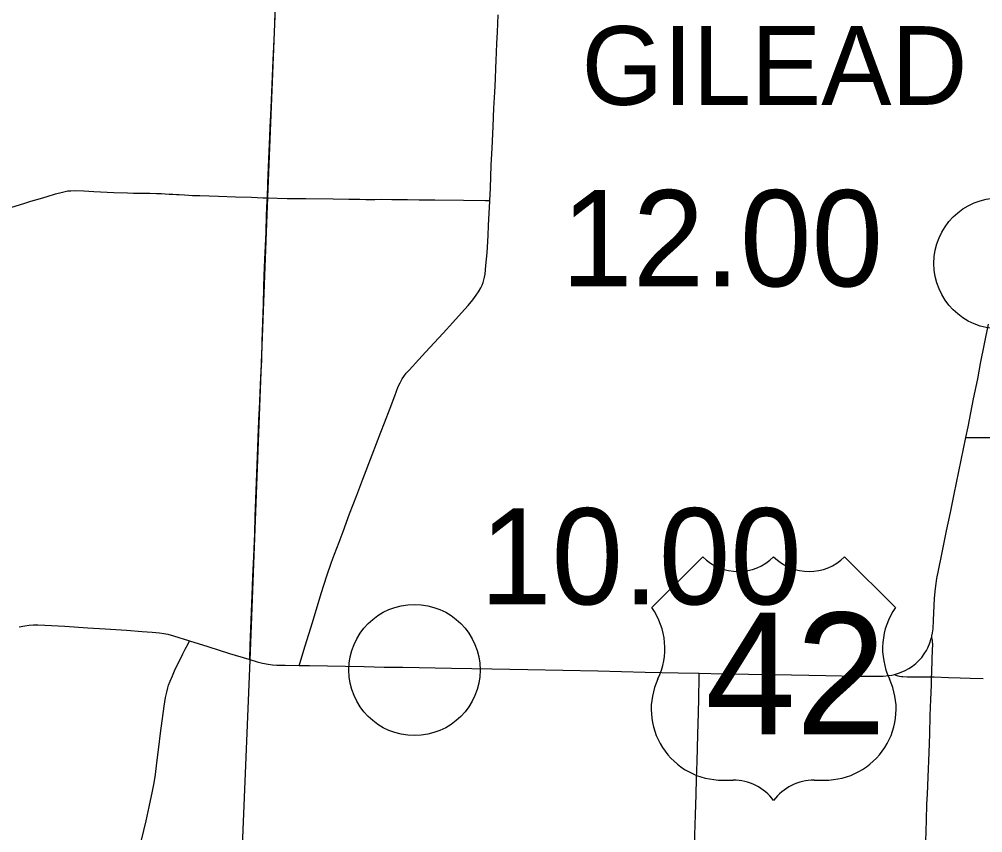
# Model space of a CAD drawing. Extents: x 1813937 to 1948437, y 826606 to 1022856.
# Drawn here: x 1864595 to 1875617, y 914870 to 924169 of the extents above; entities that cross this region are included whole.
import ezdxf

# ---------------------------------------------------------------- set-up
doc = ezdxf.new("R2010")
doc.units = 0
for name, color, linetype in [('Default', 7, 'Continuous'), ('GM_X_County_Road', 7, 'Continuous'), ('GM_X_Township', 7, 'Continuous'), ('GM_X_Township_Road', 7, 'Continuous'), ('GM_X_Township_Text', 7, 'Continuous'), ('GM_X_US_Route', 7, 'Continuous'), ('GM_X_US_Shield', 7, 'Continuous')]:
    doc.layers.add(name, color=color, linetype=linetype)

msp = doc.modelspace()

# ---------------------------------------------------------------- linework, layer by layer
at = {"layer": 'Default'}
for centre in [(1875809, 921379), (1869116, 916730)]:
    msp.add_circle(centre, 750, dxfattribs=at)
at = {"layer": 'GM_X_County_Road'}
for points in [[(1867433, 922128), (1867439, 922291), (1867450, 922570), (1867453, 922656), (1867457, 922749), (1867460, 922820), (1867466, 922939), (1867472, 923072), (1867480, 923243), (1867499, 923702), (1867513, 924013), (1867525, 924358), (1867534, 924555), (1867545, 924833), (1867550, 924964), (1867552, 925030), (1867558, 925194), (1867568, 925473), (1867576, 925670), (1867591, 926031), (1867595, 926158)], [(1867232, 916849), (1867232, 916867), (1867238, 917010), (1867259, 917584), (1867268, 917798), (1867277, 918027), (1867288, 918290), (1867294, 918486), (1867309, 918880), (1867321, 919175), (1867331, 919487), (1867340, 919670), (1867342, 919710), (1867350, 919897), (1867359, 920077), (1867368, 920274), (1867374, 920487), (1867381, 920701), (1867388, 920914), (1867393, 921111), (1867398, 921242), (1867406, 921422), (1867418, 921734), (1867425, 921931), (1867431, 922095), (1867433, 922128)], [(1875032, 916651), (1875034, 916687), (1875040, 916867), (1875045, 917030), (1875044, 917049), (1875041, 917073), (1875035, 917100), (1875033, 917111)], [(1874936, 914014), (1874938, 914048), (1874941, 914179), (1874951, 914424), (1874959, 914654), (1874965, 914769), (1874973, 915014), (1874979, 915195), (1874985, 915309), (1874992, 915506), (1875003, 915785), (1875010, 915998), (1875017, 916211), (1875023, 916392), (1875029, 916556), (1875032, 916651)]]:
    msp.add_lwpolyline(points, dxfattribs=at)
at = {"layer": 'GM_X_Township'}
msp.add_lwpolyline([(1862529, 931646), (1862452, 926319), (1863806, 926284), (1864501, 926257), (1864642, 926260), (1866861, 926186), (1867410, 926171), (1867588, 926156), (1867590, 926005), (1867433, 922134), (1867234, 916844), (1867123, 914163), (1866935, 910696)], dxfattribs=at)
at = {"layer": 'GM_X_Township_Road'}
for points in [[(1869978, 922096), (1869984, 922238), (1869995, 922500), (1870004, 922697), (1870015, 922942), (1870025, 923155), (1870036, 923336), (1870043, 923483), (1870047, 923614), (1870050, 923696), (1870059, 923893), (1870065, 924024), (1870072, 924220)], [(1864460, 922006), (1864648, 922065), (1864726, 922089), (1864836, 922121), (1864915, 922144), (1865009, 922172), (1865088, 922194), (1865120, 922201), (1865152, 922207), (1865185, 922209), (1865234, 922211), (1865332, 922208), (1865447, 922202), (1865677, 922189), (1865832, 922184), (1865903, 922183), (1865939, 922182), (1865982, 922181), (1866035, 922181), (1866088, 922180), (1866165, 922179), (1866223, 922176), (1866263, 922174), (1866309, 922171), (1866352, 922170), (1866392, 922168), (1866425, 922166), (1866485, 922162), (1866533, 922158), (1866578, 922155), (1866659, 922153), (1866873, 922148), (1867070, 922141), (1867250, 922134), (1867381, 922130), (1867433, 922128)], [(1867433, 922128), (1867660, 922122), (1867873, 922120), (1868185, 922118), (1868366, 922114), (1868490, 922112), (1868558, 922111), (1868661, 922111), (1868743, 922112), (1868858, 922110), (1869038, 922108), (1869170, 922107), (1869350, 922104), (1869678, 922101), (1869925, 922097), (1869978, 922096)], [(1867798, 916781), (1867805, 916804), (1867866, 917007), (1867948, 917274), (1868048, 917603), (1868114, 917806), (1868167, 917961), (1868200, 918054), (1868253, 918192), (1868299, 918314), (1868374, 918514), (1868457, 918729), (1868526, 918913), (1868631, 919189), (1868732, 919449), (1868774, 919556), (1868837, 919725), (1868890, 919863), (1868931, 919970), (1868951, 920014), (1868975, 920057), (1868993, 920084), (1869022, 920123), (1869055, 920159), (1869167, 920279), (1869244, 920364), (1869444, 920581), (1869554, 920703), (1869654, 920812), (1869730, 920898), (1869782, 920961), (1869822, 921014), (1869850, 921055), (1869874, 921098), (1869889, 921128), (1869902, 921159), (1869911, 921190), (1869919, 921223), (1869924, 921255), (1869934, 921353), (1869948, 921500), (1869952, 921566), (1869959, 921697), (1869964, 921812), (1869978, 922090), (1869978, 922096)], [(1875425, 919388), (1875471, 919389), (1875570, 919389), (1875750, 919387)], [(1865994, 914783), (1866045, 915007), (1866080, 915167), (1866119, 915343), (1866138, 915439), (1866153, 915536), (1866169, 915667), (1866191, 915846), (1866211, 916008), (1866254, 916317), (1866269, 916414), (1866282, 916478), (1866294, 916526), (1866304, 916557), (1866321, 916603), (1866347, 916663), (1866380, 916738), (1866423, 916826), (1866466, 916915), (1866494, 916969), (1866526, 917031), (1866542, 917064)], [(1872301, 914032), (1872302, 914059), (1872305, 914141), (1872314, 914436), (1872318, 914633), (1872324, 914846), (1872332, 915076), (1872339, 915305), (1872343, 915486), (1872349, 915683), (1872358, 915994), (1872364, 916240), (1872368, 916404), (1872373, 916650), (1872374, 916692)], [(1874606, 916678), (1874624, 916671), (1874645, 916663), (1874663, 916659), (1874686, 916655), (1874702, 916654), (1874752, 916652), (1874867, 916651), (1875032, 916651)], [(1875032, 916651), (1875063, 916651), (1875227, 916644), (1875358, 916640), (1875473, 916637), (1875621, 916634)]]:
    msp.add_lwpolyline(points, dxfattribs=at)
at = {"layer": 'GM_X_US_Route'}
for points in [[(1874996, 917002), (1875007, 917028), (1875028, 917091), (1875033, 917111), (1875036, 917122), (1875042, 917154), (1875048, 917202), (1875054, 917300), (1875065, 917546), (1875071, 917628), (1875079, 917694), (1875092, 917775), (1875141, 918016), (1875184, 918225), (1875204, 918321), (1875247, 918530), (1875291, 918739), (1875425, 919388), (1875450, 919510), (1875513, 919832), (1875559, 920057), (1875593, 920235), (1875682, 920685)], [(1864593, 917223), (1864658, 917235), (1864707, 917241), (1864757, 917245), (1864806, 917246), (1864888, 917243), (1865118, 917230), (1865380, 917212), (1865576, 917199), (1865822, 917184), (1866002, 917172), (1866116, 917164), (1866198, 917156), (1866247, 917149), (1866295, 917138), (1866359, 917121), (1866531, 917068), (1866542, 917064), (1866751, 916999), (1867001, 916920), (1867220, 916852), (1867232, 916849), (1867315, 916825), (1867378, 916809), (1867443, 916797), (1867491, 916791), (1867540, 916787), (1867638, 916784), (1867798, 916781), (1867917, 916780), (1868327, 916773), (1868540, 916769), (1868770, 916764), (1868983, 916761), (1869541, 916751), (1869771, 916746), (1870001, 916743), (1870411, 916735), (1871214, 916719), (1871756, 916706), (1872133, 916697), (1872374, 916692), (1872642, 916686), (1872937, 916681), (1873150, 916678), (1873429, 916673), (1873626, 916670), (1873823, 916667), (1874184, 916661), (1874397, 916659), (1874479, 916661), (1874544, 916666), (1874576, 916671), (1874606, 916678), (1874654, 916692), (1874685, 916704), (1874729, 916724), (1874772, 916748), (1874813, 916774), (1874851, 916804), (1874886, 916838), (1874919, 916874), (1874948, 916913), (1874974, 916954), (1874989, 916983), (1874996, 917002)]]:
    msp.add_lwpolyline(points, dxfattribs=at)
at = {"layer": 'GM_X_US_Shield'}
for p, q in [((1872413, 918023), (1871833, 917443)), ((1874618, 917443), (1874037, 918023)), ((1872645, 915471), (1872761, 915471)), ((1873689, 915471), (1873805, 915471))]:
    msp.add_line(p, q, dxfattribs=at)
for centre, radius, start, end in [((1872819, 918437), 580, 225.573, 314.427), ((1873631, 918437), 580, 225.573, 314.427), ((1871168, 916977), 812, 334.5471, 35.0009), ((1875283, 916977), 812, 144.9991, 205.4529), ((1872636, 916283), 812, 154.8319, 270.6383), ((1873814, 916283), 812, 269.3617, 25.1681), ((1872761, 914891), 580, 36.8699, 90), ((1873689, 914891), 580, 90, 143.1301)]:
    msp.add_arc(centre, radius, start, end, dxfattribs=at)

# ---------------------------------------------------------------- texts
at = {"layer": 'Default'}
for s, p in [('12.00', (1870795, 921116)), ('10.00', (1869866, 917480))]:
    msp.add_text(s, height=1100, dxfattribs=at).set_placement(p)
at = {"layer": 'GM_X_Township_Text'}
msp.add_text('GILEAD', height=900, rotation=0, dxfattribs=at).set_placement((1871027, 923191))
at = {"layer": 'GM_X_US_Shield'}
msp.add_text('42', height=1392.2, dxfattribs=at).set_placement((1872442, 915993))

doc.saveas('drawing.dxf')
